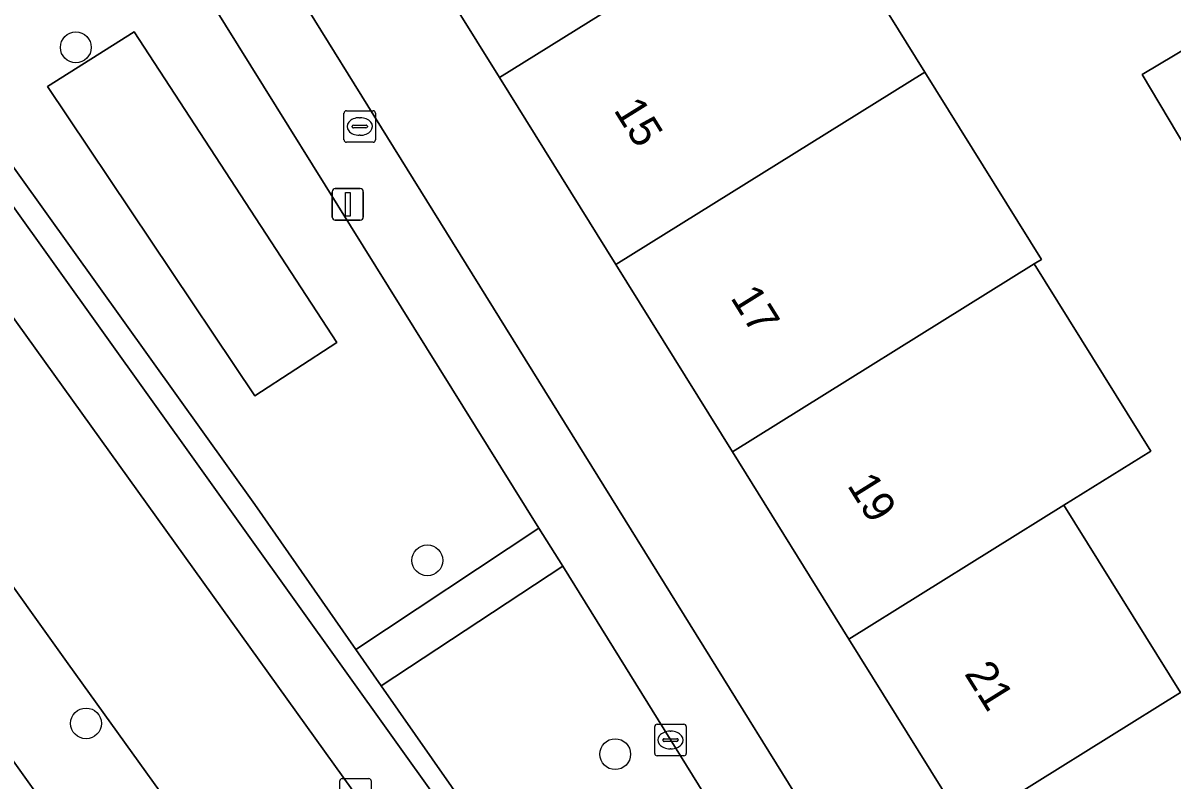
# Model space of a CAD drawing. Extents: x 162523 to 163266, y 381230 to 382050.
# Drawn here: x 162717.86 to 162754.37, y 381810.31 to 381834.37 of the extents above; entities that cross this region are included whole.
import ezdxf

# ---------------------------------------------------------------- set-up
doc = ezdxf.new("R2010")
doc.units = 0
for name, color, linetype in [('IMGEO_Boom', 7, 'Continuous'), ('IMGEO_Erf', 7, 'Continuous'), ('IMGEO_Groenvoorziening', 7, 'Continuous'), ('IMGEO_Kolk', 7, 'Continuous'), ('IMGEO_Lichtmast', 7, 'Continuous'), ('IMGEO_Pand', 7, 'Continuous'), ('IMGEO_Pand_nummerreeks', 7, 'Continuous'), ('IMGEO_Parkeervlak_open', 7, 'Continuous'), ('IMGEO_Rijbaan_lokaal_open', 7, 'Continuous'), ('IMGEO_Rioolput', 7, 'Continuous'), ('IMGEO_Voetpad_open', 7, 'Continuous')]:
    doc.layers.add(name, color=color, linetype=linetype)

msp = doc.modelspace()

# ---------------------------------------------------------------- linework, layer by layer
at = {"layer": 'IMGEO_Boom'}
for centre in [(162719.533, 381833.599), (162730.694, 381817.315), (162719.856, 381812.14), (162736.659, 381811.164)]:
    msp.add_circle(centre, 0.489, dxfattribs=at)
at = {"layer": 'IMGEO_Erf'}
for points in [[(162703.711, 381872.133), (162752.202, 381794.074), (162753.849, 381791.703), (162766.887, 381796.3), (162774.478, 381798.601), (162772.186, 381805.655), (162769.657, 381810.036), (162767.262, 381808.65), (162765.58, 381811.556), (162767.975, 381812.942), (162767.323, 381814.077), (162761.902, 381823.466), (162759.129, 381828.269), (162758.953, 381828.164), (162758.554, 381827.926), (162756.86, 381826.917), (162755.075, 381829.911), (162753.392, 381832.737), (162755.485, 381833.984), (162755.731, 381834.13), (162752.78, 381839.267), (162738.115, 381864.612)], [(162755.508, 381796.448), (162751.474, 381802.93), (162747.776, 381808.873), (162744.077, 381814.816), (162740.379, 381820.759), (162736.68, 381826.702), (162732.981, 381832.645), (162729.283, 381838.588), (162725.584, 381844.531), (162721.886, 381850.474), (162718.187, 381856.418), (162714.489, 381862.36), (162710.79, 381868.304)], [(162724.325, 381868.486), (162728.024, 381862.543), (162725.018, 381860.672), (162728.717, 381854.728), (162732.415, 381848.785), (162734.568, 381850.126), (162738.268, 381844.183), (162741.968, 381838.241), (162742.796, 381838.756), (162746.493, 381832.814), (162750.193, 381826.869), (162749.966, 381826.728), (162753.664, 381820.786), (162750.907, 381819.07), (162754.606, 381813.126)], [(162733.516, 381788.621), (162685.191, 381856.189)]]:
    msp.add_lwpolyline(points, dxfattribs=at)
at = {"layer": 'IMGEO_Groenvoorziening'}
for points in [[(162719.105, 381842.623), (162711.887, 381837.703), (162725.214, 381819.087), (162728.423, 381814.491), (162734.234, 381818.334)], [(162725.215, 381822.539), (162718.637, 381832.355), (162721.383, 381834.088), (162727.821, 381824.235)], [(162725.215, 381822.539), (162727.821, 381824.235), (162721.383, 381834.088), (162718.637, 381832.355)]]:
    msp.add_lwpolyline(points, close=True, dxfattribs=at)
for points in [[(162734.998, 381817.128), (162729.229, 381813.337), (162733.079, 381807.822), (162740.762, 381797.112)], [(162747.87, 381796.391), (162734.998, 381817.128)]]:
    msp.add_lwpolyline(points, dxfattribs=at)
at = {"layer": 'IMGEO_Kolk'}
for p, q in [((162737.914, 381811.187), (162737.914, 381812.039)), ((162737.989, 381812.113), (162738.841, 381812.113)), ((162738.915, 381812.039), (162738.915, 381811.187)), ((162738.173, 381811.607), (162738.173, 381811.619)), ((162738.611, 381811.57), (162738.213, 381811.57)), ((162738.216, 381811.656), (162738.614, 381811.656)), ((162738.402, 381811.893), (162738.427, 381811.893)), ((162738.657, 381811.619), (162738.657, 381811.607)), ((162738.425, 381811.333), (162738.4, 381811.333)), ((162738.841, 381811.113), (162737.989, 381811.113)), ((162727.911, 381809.461), (162727.911, 381810.313)), ((162727.986, 381810.387), (162728.838, 381810.387)), ((162728.912, 381810.313), (162728.912, 381809.461))]:
    msp.add_line(p, q, dxfattribs=at)
for points in [[(162737.914, 381811.187), (162737.914, 381812.039)], [(162737.989, 381812.113), (162738.841, 381812.113)], [(162738.915, 381812.039), (162738.915, 381811.187)], [(162738.841, 381811.113), (162737.989, 381811.113)], [(162727.911, 381809.461), (162727.911, 381810.313)], [(162727.986, 381810.387), (162728.838, 381810.387)], [(162728.912, 381810.313), (162728.912, 381809.461)]]:
    msp.add_lwpolyline(points, dxfattribs=at)
for centre, radius, start, end in [((162737.991, 381812.037), 0.0765, 91.552, 178.448), ((162737.991, 381812.037), 0.0765, 91.552, 178.448), ((162738.839, 381812.037), 0.0765, 1.552, 88.448), ((162738.839, 381812.037), 0.0765, 1.552, 88.448), ((162738.213, 381811.616), 0.0403, 85.8775, 175.7526), ((162738.21, 381811.606), 0.0366, 178.938, 274.7102), ((162738.614, 381811.613), 0.043, 264.8664, 352.4533), ((162738.618, 381811.618), 0.0386, 1.7309, 96.639), ((162737.991, 381811.189), 0.0765, 181.552, 268.448), ((162737.991, 381811.189), 0.0765, 181.552, 268.448), ((162738.839, 381811.189), 0.0765, 271.552, 358.448), ((162738.839, 381811.189), 0.0765, 271.552, 358.448), ((162727.988, 381810.311), 0.0765, 91.552, 178.448), ((162727.988, 381810.311), 0.0765, 91.552, 178.448), ((162728.836, 381810.311), 0.0765, 1.552, 88.448), ((162728.836, 381810.311), 0.0765, 1.552, 88.448)]:
    msp.add_arc(centre, radius, start, end, dxfattribs=at)
for centre, major_axis, ratio, start_param, end_param in [((162738.401, 381811.613), (-0.387, 0.002), 0.722429, 4.712389, 7.853982), ((162738.426, 381811.613), (-0.39, 0.002), 0.717154, 1.570796, 4.712389)]:
    msp.add_ellipse(centre, major_axis=major_axis, ratio=ratio, start_param=start_param, end_param=end_param, dxfattribs=at)
at = {"layer": 'IMGEO_Lichtmast'}
for p, q in [((162727.77, 381829.114), (162728.56, 381829.114)), ((162728.56, 381829.114), (162727.77, 381829.114)), ((162727.67, 381828.214), (162727.67, 381829.014)), ((162727.67, 381829.014), (162727.67, 381828.214)), ((162728.66, 381829.014), (162728.66, 381828.214)), ((162728.66, 381828.214), (162728.66, 381829.014)), ((162728.56, 381828.114), (162727.77, 381828.114)), ((162727.77, 381828.114), (162728.56, 381828.114))]:
    msp.add_line(p, q, dxfattribs=at)
msp.add_lwpolyline([(162728.09, 381828.989), (162728.24, 381828.989), (162728.24, 381828.239), (162728.09, 381828.239), (162728.09, 381828.989)], dxfattribs=at)
for centre, start, end in [((162727.77, 381829.014), 90, 180), ((162727.77, 381829.014), 90, 180), ((162728.56, 381829.014), 0, 90), ((162728.56, 381829.014), 360, 90), ((162727.77, 381828.214), 180, 270), ((162727.77, 381828.214), 180, 270), ((162728.56, 381828.214), 270, 0), ((162728.56, 381828.214), 270, 0)]:
    msp.add_arc(centre, 0.1, start, end, dxfattribs=at)
at = {"layer": 'IMGEO_Pand'}
for points in [[(162741.968, 381838.241), (162738.268, 381844.183), (162736.114, 381842.842), (162729.283, 381838.588), (162732.981, 381832.645), (162739.812, 381836.899)], [(162742.796, 381838.756), (162741.968, 381838.241), (162739.812, 381836.899), (162732.981, 381832.645), (162736.68, 381826.702), (162746.493, 381832.814)], [(162755.731, 381834.13), (162755.485, 381833.984), (162753.392, 381832.737), (162755.075, 381829.911), (162756.935, 381831.07), (162757.144, 381831.2), (162757.386, 381831.351)], [(162750.193, 381826.869), (162746.493, 381832.814), (162736.68, 381826.702), (162740.379, 381820.759), (162749.966, 381826.728)], [(162749.966, 381826.728), (162740.379, 381820.759), (162744.077, 381814.816), (162750.907, 381819.07), (162753.664, 381820.786)], [(162744.077, 381814.816), (162747.776, 381808.873), (162754.606, 381813.126), (162750.907, 381819.07)], [(162759.636, 381811.361), (162758.278, 381811.545), (162756.544, 381814.333), (162754.606, 381813.126), (162747.776, 381808.873), (162751.474, 381802.93), (162758.304, 381807.184), (162760.128, 381808.319), (162760.276, 381808.41), (162760.552, 381809.89)]]:
    msp.add_lwpolyline(points, close=True, dxfattribs=at)
at = {"layer": 'IMGEO_Parkeervlak_open'}
for points in [[(162693.495, 381858.692), (162703.613, 381844.475), (162715.566, 381827.76), (162728.313, 381810.023), (162740.722, 381792.594)], [(162740.249, 381796.81), (162697.482, 381856.586)]]:
    msp.add_lwpolyline(points, dxfattribs=at)
at = {"layer": 'IMGEO_Rijbaan_lokaal_open'}
for points in [[(162728.313, 381810.023), (162715.566, 381827.76), (162703.613, 381844.475), (162693.495, 381858.692), (162693.324, 381858.932)], [(162689.021, 381856.614), (162693.329, 381850.547), (162703.538, 381836.077), (162719.288, 381814.036), (162729.638, 381799.644), (162737.359, 381788.833), (162740.416, 381785.225)]]:
    msp.add_lwpolyline(points, dxfattribs=at)
at = {"layer": 'IMGEO_Rioolput'}
for p, q in [((162728.047, 381830.661), (162728.047, 381831.513)), ((162728.122, 381831.587), (162728.974, 381831.587)), ((162728.535, 381831.367), (162728.56, 381831.367)), ((162729.048, 381831.513), (162729.048, 381830.661)), ((162728.306, 381831.081), (162728.306, 381831.093)), ((162728.744, 381831.044), (162728.346, 381831.044)), ((162728.349, 381831.13), (162728.747, 381831.13)), ((162728.79, 381831.093), (162728.79, 381831.081)), ((162728.974, 381830.587), (162728.122, 381830.587)), ((162728.558, 381830.807), (162728.533, 381830.807))]:
    msp.add_line(p, q, dxfattribs=at)
for points in [[(162728.047, 381830.661), (162728.047, 381831.513)], [(162728.122, 381831.587), (162728.974, 381831.587)], [(162729.048, 381831.513), (162729.048, 381830.661)], [(162728.974, 381830.587), (162728.122, 381830.587)]]:
    msp.add_lwpolyline(points, dxfattribs=at)
for centre, radius, start, end in [((162728.124, 381831.511), 0.0765, 91.552, 178.448), ((162728.124, 381831.511), 0.0765, 91.552, 178.448), ((162728.972, 381831.511), 0.0765, 1.552, 88.448), ((162728.972, 381831.511), 0.0765, 1.552, 88.448), ((162728.346, 381831.09), 0.0403, 85.8775, 175.7526), ((162728.343, 381831.08), 0.0366, 178.938, 274.7102), ((162728.747, 381831.087), 0.043, 264.8664, 352.4533), ((162728.751, 381831.092), 0.0386, 1.7309, 96.639), ((162728.124, 381830.663), 0.0765, 181.552, 268.448), ((162728.124, 381830.663), 0.0765, 181.552, 268.448), ((162728.972, 381830.663), 0.0765, 271.552, 358.448), ((162728.972, 381830.663), 0.0765, 271.552, 358.448)]:
    msp.add_arc(centre, radius, start, end, dxfattribs=at)
for centre, major_axis, ratio, start_param, end_param in [((162728.534, 381831.087), (-0.387, 0.002), 0.722429, 4.712389, 7.853982), ((162728.559, 381831.087), (-0.39, 0.002), 0.717154, 1.570796, 4.712389)]:
    msp.add_ellipse(centre, major_axis=major_axis, ratio=ratio, start_param=start_param, end_param=end_param, dxfattribs=at)
at = {"layer": 'IMGEO_Voetpad_open'}
for points in [[(162747.925, 381792.231), (162752.202, 381794.074), (162703.711, 381872.133)], [(162703.289, 381868.189), (162718.394, 381843.879), (162719.105, 381842.623), (162734.234, 381818.334), (162734.998, 381817.128), (162747.87, 381796.391)], [(162687.52, 381857.934), (162685.191, 381856.189), (162733.516, 381788.621)], [(162740.762, 381797.112), (162733.079, 381807.822), (162729.229, 381813.337), (162728.423, 381814.491), (162725.214, 381819.087), (162711.887, 381837.703), (162711.041, 381838.922), (162697.58, 381857.674)], [(162697.482, 381856.586), (162740.249, 381796.81)], [(162740.416, 381785.225), (162737.359, 381788.833), (162729.638, 381799.644), (162719.288, 381814.036), (162703.538, 381836.077), (162693.329, 381850.547)]]:
    msp.add_lwpolyline(points, dxfattribs=at)
msp.add_lwpolyline([(162734.998, 381817.128), (162734.234, 381818.334), (162728.423, 381814.491), (162729.229, 381813.337)], close=True, dxfattribs=at)

# ---------------------------------------------------------------- texts
at = {"layer": 'IMGEO_Pand_nummerreeks'}
for s, rotation, p in [('15', 301.8963, (162736.591, 381831.613)), ('17', 301.8963, (162740.298, 381825.655)), ('19', 301.8963, (162744.006, 381819.698)), ('21', 301.8952, (162747.726, 381813.722))]:
    msp.add_text(s, height=1, rotation=rotation, dxfattribs=at).set_placement(p)

doc.saveas('drawing.dxf')
